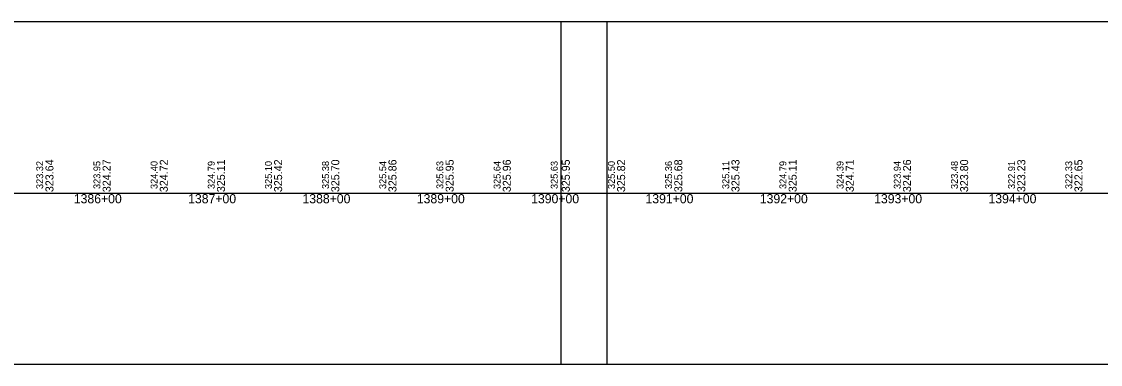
# Model space of a CAD drawing. Extents: x 2898 to 49495, y -15038 to -13538.
# Drawn here: x 27983 to 28927, y -15038 to -14738 of the extents above; entities that cross this region are included whole.
import ezdxf

# ---------------------------------------------------------------- set-up
doc = ezdxf.new("R2010")
doc.units = 0
for name, color, linetype in [('RD_DDB_StaTX', 7, 'Continuous'), ('RD_DDB_StripGrade', 7, 'Continuous'), ('RD_GPK_Profile_Cell', 7, 'Continuous'), ('RD_SHT_ShtClip', 7, 'Continuous')]:
    doc.layers.add(name, color=color, linetype=linetype)

msp = doc.modelspace()

# ---------------------------------------------------------------- linework, layer by layer
at = {"layer": 'RD_GPK_Profile_Cell'}
msp.add_line((2976.05, -14888.47), (48721.13, -14888.47), dxfattribs=at)
at = {"layer": 'RD_SHT_ShtClip'}
for points in [[(26955.38, -14738.47), (28495.38, -14738.47), (28495.38, -15038.47), (26955.38, -15038.47)], [(28455.38, -14738.47), (29995.38, -14738.47), (29995.38, -15038.47), (28455.38, -15038.47)]]:
    msp.add_lwpolyline(points, close=True, dxfattribs=at)

# ---------------------------------------------------------------- texts
at = {"layer": 'RD_DDB_StaTX'}
for s, p in [('1386+00', (28029.18, -14897.47)), ('1387+00', (28129.18, -14897.47)), ('1388+00', (28229.18, -14897.47)), ('1389+00', (28329.18, -14897.47)), ('1390+00', (28429.18, -14897.47)), ('1391+00', (28529.18, -14897.47)), ('1392+00', (28629.18, -14897.47)), ('1393+00', (28729.18, -14897.47)), ('1394+00', (28829.18, -14897.47))]:
    msp.add_text(s, height=8, dxfattribs=at).set_placement(p)
at = {"layer": 'RD_DDB_StripGrade'}
for s, height, p in [('323.32', 6, (28002.38, -14884.98)), ('323.64', 7, (28011.38, -14887.72)), ('323.95', 6, (28052.38, -14884.98)), ('324.27', 7, (28061.38, -14887.72)), ('324.40', 6, (28102.38, -14884.98)), ('324.72', 7, (28111.38, -14887.72)), ('324.79', 6, (28152.38, -14884.98)), ('325.11', 7, (28161.38, -14887.72)), ('325.10', 6, (28202.38, -14884.98)), ('325.42', 7, (28211.38, -14887.72)), ('325.38', 6, (28252.38, -14884.98)), ('325.70', 7, (28261.38, -14887.72)), ('325.54', 6, (28302.38, -14884.98)), ('325.86', 7, (28311.38, -14887.72)), ('325.63', 6, (28352.38, -14884.98)), ('325.95', 7, (28361.38, -14887.72)), ('325.64', 6, (28402.38, -14884.98)), ('325.96', 7, (28411.38, -14887.72)), ('325.63', 6, (28452.38, -14884.98)), ('325.95', 7, (28463, -14887.72)), ('325.50', 6, (28502.38, -14884.98)), ('325.82', 7, (28511.38, -14887.72)), ('325.36', 6, (28552.38, -14884.98)), ('325.68', 7, (28561.38, -14887.72)), ('325.11', 6, (28602.38, -14884.98)), ('325.43', 7, (28611.38, -14887.72)), ('324.79', 6, (28652.38, -14884.98)), ('325.11', 7, (28661.38, -14887.72)), ('324.39', 6, (28702.38, -14884.98)), ('324.71', 7, (28711.38, -14887.72)), ('323.94', 6, (28752.38, -14884.98)), ('324.26', 7, (28761.38, -14887.72)), ('323.48', 6, (28802.38, -14884.98)), ('323.80', 7, (28811.38, -14887.72)), ('322.91', 6, (28852.38, -14884.98)), ('323.23', 7, (28861.38, -14887.72)), ('322.33', 6, (28902.38, -14884.98)), ('322.65', 7, (28911.38, -14887.72))]:
    msp.add_text(s, height=height, rotation=90, dxfattribs=at).set_placement(p)

doc.saveas('drawing.dxf')
